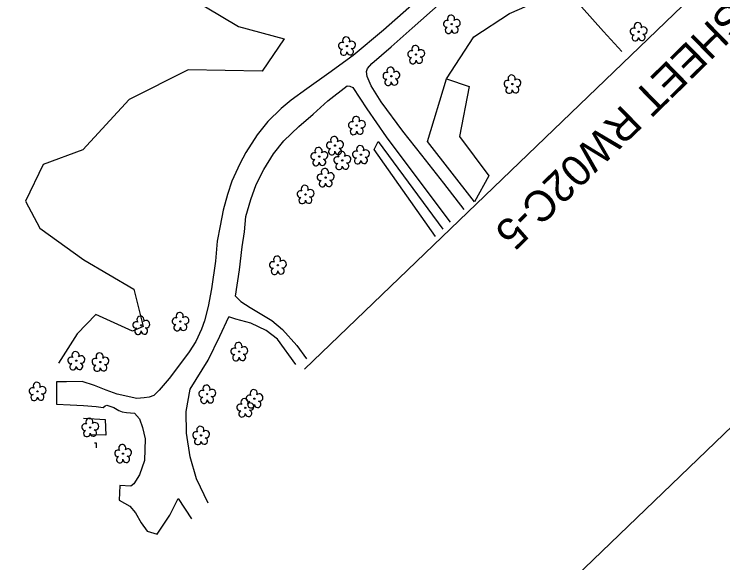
# Model space of a CAD drawing. Extents: x 473158 to 477500, y 500738 to 505114.
# Drawn here: x 475616.1 to 475983.4, y 501414.7 to 501699.2 of the extents above; entities that cross this region are included whole.
import ezdxf

# ---------------------------------------------------------------- set-up
doc = ezdxf.new("R2010")
doc.units = 0
for name, color, linetype in [('CTL Sheet Border CELL', 7, 'Continuous'), ('Exist Other Culture Area Outline', 7, 'Continuous'), ('Exist Roads Soil', 7, 'Continuous'), ('Exist Vegetation Hedge Row', 7, 'Continuous'), ('Exist Vegetation Tree CELL', 7, 'Continuous'), ('Exist Vegetation Woods Line', 7, 'Continuous'), ('Matchline', 7, 'Continuous'), ('Matchline Text', 7, 'Continuous')]:
    doc.layers.add(name, color=color, linetype=linetype)

msp = doc.modelspace()

# ---------------------------------------------------------------- linework, layer by layer
at = {"layer": 'CTL Sheet Border CELL'}
msp.add_lwpolyline([(473224.2, 503436.31), (475527.63, 501042.56), (477203.24, 502654.95), (474899.8, 505048.7)], close=True, dxfattribs=at)
at = {"layer": 'Exist Other Culture Area Outline'}
for points in [[(475651.96, 501489.64), (475663.24, 501489.08), (475663.53, 501480.96), (475655.8, 501481.12)], [(475658.85, 501474.35), (475658.86, 501476.71), (475657.76, 501476.76)]]:
    msp.add_lwpolyline(points, dxfattribs=at)
at = {"layer": 'Exist Roads Soil'}
for points in [[(475849.31, 501597.94), (475838.76, 501611.62), (475827.36, 501626.14), (475817.57, 501638.52), (475806.28, 501653.8), (475801.13, 501662.09), (475799.04, 501666.86), (475798.74, 501669.55), (475799.27, 501671.07), (475801.55, 501673.54), (475811.52, 501682.32), (475822.32, 501691.88), (475837.47, 501705.27), (475856.84, 501721.99), (475870.17, 501733), (475888.6, 501747.32), (475901.67, 501758.36), (475911.09, 501765.57), (475915.17, 501767.66), (475920.89, 501768.24), (475926.56, 501768.26)], [(475830.78, 501711.61), (475807.52, 501690.93), (475791.8, 501677.7), (475779.23, 501668.59), (475767.81, 501660.49), (475759.68, 501654.65), (475754.45, 501650.31), (475747.62, 501643.6), (475741.99, 501636.63)], [(475730.76, 501552.91), (475732.96, 501566.53), (475734.34, 501578.55), (475735.51, 501586.32), (475736.22, 501594.24), (475738.71, 501603.08), (475741.5, 501610.93), (475745.44, 501618.64), (475750.59, 501626.74), (475755.88, 501633.49), (475763.58, 501640.88), (475771.08, 501647.42), (475778.75, 501654.23), (475788.78, 501662.04), (475790.15, 501661.92), (475791.61, 501661.17), (475798.92, 501650.1), (475808.87, 501635.6), (475825.81, 501612.98), (475842.1, 501591.31)], [(475741.99, 501636.63), (475736.11, 501627.5), (475733.15, 501621.58), (475728.98, 501612.62), (475726.6, 501605.7), (475724.49, 501597.56), (475722.92, 501589.45), (475721.36, 501581.54), (475720.41, 501571.07), (475718.38, 501556.77), (475716.64, 501547.54), (475714.74, 501540.21), (475713.14, 501535.89), (475710.22, 501529.43), (475706.89, 501524.12), (475701.78, 501517.3), (475696.52, 501510.24), (475691.28, 501504.17), (475688.43, 501501.5), (475686.11, 501500.5), (475683.52, 501500.17), (475679.76, 501499.88), (475669.57, 501502.16), (475663.81, 501504.3), (475657.7, 501506.64), (475651.31, 501508.68), (475643.31, 501508.52), (475637.97, 501508.54), (475637.96, 501497.01), (475645.14, 501496.69), (475652.02, 501496.33), (475658.52, 501495.75), (475662.26, 501495.14), (475663.23, 501496.08), (475664.05, 501496.48), (475667.75, 501495.25), (475670.27, 501493.74), (475672, 501493), (475674.34, 501492.64), (475678.42, 501492.24), (475680.99, 501489.32), (475682.57, 501484.93), (475683.97, 501478.91), (475683.67, 501467.72), (475681.04, 501460.38), (475678.07, 501455.7), (475676.51, 501454.36), (475670.9, 501454.77), (475670.61, 501447.15), (475676.02, 501444.03), (475679, 501440.65), (475681.96, 501435.42), (475685.06, 501431.06), (475690.18, 501429.61), (475696.79, 501439.45), (475701.17, 501447.98), (475708.07, 501437.42)], [(475730.76, 501552.91), (475733.53, 501550.14), (475738.44, 501547.16), (475749.58, 501540.31), (475755.11, 501535.75), (475762.57, 501527.36), (475767.66, 501520.54)], [(475716.61, 501445.64), (475710.56, 501458.27), (475707.35, 501469.61), (475705.38, 501481.9), (475705.18, 501493.16), (475707.33, 501504.81), (475716.63, 501519.72), (475722.71, 501532.17), (475727.38, 501542.16)], [(475762.14, 501517.56), (475752.65, 501530.58), (475746.71, 501535.15), (475738.79, 501538.92), (475730.98, 501540.99), (475727.38, 501542.16)]]:
    msp.add_lwpolyline(points, dxfattribs=at)
at = {"layer": 'Exist Vegetation Hedge Row'}
msp.add_lwpolyline([(475840.13, 501665.63), (475854.3, 501687.47), (475872.85, 501699.59), (475897.94, 501710.57), (475904.37, 501709.63), (475921.52, 501690.15), (475931.11, 501679.81)], dxfattribs=at)
at = {"layer": 'Exist Vegetation Tree CELL'}
for p, q in [((475842.91, 501694.01), (475842.91, 501694.01)), ((475939.76, 501690.1), (475939.76, 501690.1)), ((475788.59, 501682.65), (475788.59, 501682.65)), ((475824.42, 501678.29), (475824.42, 501678.29)), ((475811.59, 501667.01), (475811.59, 501667.01)), ((475874.32, 501662.94), (475874.32, 501662.94)), ((475793.67, 501641.49), (475793.67, 501641.49)), ((475782.39, 501631.03), (475782.39, 501631.03)), ((475774.23, 501625.35), (475774.23, 501625.35)), ((475795.84, 501626.32), (475795.84, 501626.32)), ((475786.15, 501623.36), (475786.15, 501623.36)), ((475777.54, 501614.44), (475777.54, 501614.44)), ((475767.09, 501605.72), (475767.09, 501605.72)), ((475752.76, 501568.99), (475752.76, 501568.99)), ((475681.95, 501537.85), (475681.95, 501537.85)), ((475702.27, 501539.82), (475702.27, 501539.82)), ((475732.74, 501524.19), (475732.74, 501524.19)), ((475648.29, 501519.51), (475648.29, 501519.51)), ((475660.77, 501518.77), (475660.77, 501518.77)), ((475628.21, 501503.59), (475628.21, 501503.59)), ((475716.15, 501502.16), (475716.15, 501502.16)), ((475740.62, 501499.8), (475740.62, 501499.8)), ((475735.88, 501495.08), (475735.88, 501495.08)), ((475655.48, 501484.9), (475655.48, 501484.9)), ((475712.96, 501480.74), (475712.96, 501480.74)), ((475672.53, 501471.3), (475672.53, 501471.3))]:
    msp.add_line(p, q, dxfattribs=at)
for centre in [(475842.91, 501694.01), (475939.76, 501690.1), (475788.59, 501682.65), (475824.42, 501678.29), (475811.59, 501667.01), (475874.32, 501662.94), (475793.67, 501641.49), (475782.39, 501631.03), (475774.23, 501625.35), (475795.84, 501626.32), (475786.15, 501623.36), (475777.54, 501614.44), (475767.09, 501605.72), (475752.76, 501568.99), (475681.95, 501537.85), (475702.27, 501539.82), (475732.74, 501524.19), (475648.29, 501519.51), (475660.77, 501518.77), (475628.21, 501503.59), (475716.15, 501502.16), (475740.62, 501499.8), (475735.88, 501495.08), (475655.48, 501484.9), (475712.96, 501480.74), (475672.53, 501471.3)]:
    msp.add_circle(centre, 0.326, dxfattribs=at)
for centre, radius, start, end in [((475842.52, 501696.88), 1.86, 330.1651, 219.7134), ((475840.3, 501694.16), 1.73, 62.6636, 279.3457), ((475845.45, 501694.6), 1.9, 257.1011, 134.1999), ((475939.38, 501692.97), 1.86, 330.1651, 219.7134), ((475841.2, 501690.89), 1.69, 111.5671, 6.231), ((475844.58, 501691.11), 1.7, 181.2822, 74.56), ((475937.16, 501690.25), 1.73, 62.6636, 279.3457), ((475942.31, 501690.69), 1.9, 257.1011, 134.1999), ((475938.06, 501686.98), 1.69, 111.5671, 6.231), ((475941.43, 501687.2), 1.7, 181.2822, 74.56), ((475785.98, 501682.81), 1.73, 62.6636, 279.3457), ((475788.2, 501685.53), 1.86, 330.1651, 219.7134), ((475791.14, 501683.24), 1.9, 257.1011, 134.1999), ((475786.88, 501679.53), 1.69, 111.5671, 6.231), ((475790.26, 501679.75), 1.7, 181.2822, 74.56), ((475821.82, 501678.45), 1.73, 62.6636, 279.3457), ((475824.04, 501681.17), 1.86, 330.1651, 219.7134), ((475826.97, 501678.88), 1.9, 257.1011, 134.1999), ((475822.72, 501675.17), 1.69, 111.5671, 6.231), ((475826.09, 501675.4), 1.7, 181.2822, 74.56), ((475811.2, 501669.88), 1.86, 330.1651, 219.7134), ((475814.14, 501667.59), 1.9, 257.1011, 134.1999), ((475808.98, 501667.16), 1.73, 62.6636, 279.3457), ((475809.89, 501663.89), 1.69, 111.5671, 6.231), ((475813.26, 501664.11), 1.7, 181.2822, 74.56), ((475873.93, 501665.81), 1.86, 330.1651, 219.7134), ((475876.87, 501663.53), 1.9, 257.1011, 134.1999), ((475871.71, 501663.09), 1.73, 62.6636, 279.3457), ((475872.61, 501659.82), 1.69, 111.5671, 6.231), ((475875.99, 501660.04), 1.7, 181.2822, 74.56), ((475791.06, 501641.64), 1.73, 62.6636, 279.3457), ((475793.28, 501644.36), 1.86, 330.1651, 219.7134), ((475796.22, 501642.08), 1.9, 257.1011, 134.1999), ((475791.96, 501638.37), 1.69, 111.5671, 6.231), ((475795.34, 501638.59), 1.7, 181.2822, 74.56), ((475779.78, 501631.19), 1.73, 62.6636, 279.3457), ((475782, 501633.91), 1.86, 330.1651, 219.7134), ((475784.94, 501631.62), 1.9, 257.1011, 134.1999), ((475773.84, 501628.22), 1.86, 330.1651, 219.7134), ((475780.69, 501627.91), 1.69, 111.5671, 6.231), ((475784.06, 501628.13), 1.7, 181.2822, 74.56), ((475795.45, 501629.19), 1.86, 330.1651, 219.7134), ((475798.39, 501626.91), 1.9, 257.1011, 134.1999), ((475771.62, 501625.51), 1.73, 62.6636, 279.3457), ((475776.78, 501625.94), 1.9, 257.1011, 134.1999), ((475783.55, 501623.51), 1.73, 62.6636, 279.3457), ((475785.77, 501626.23), 1.86, 330.1651, 219.7134), ((475788.7, 501623.95), 1.9, 257.1011, 134.1999), ((475793.23, 501626.47), 1.73, 62.6636, 279.3457), ((475797.51, 501623.42), 1.7, 181.2822, 74.56), ((475772.52, 501622.23), 1.69, 111.5671, 6.231), ((475775.9, 501622.45), 1.7, 181.2822, 74.56), ((475784.45, 501620.24), 1.69, 111.5671, 6.231), ((475787.83, 501620.46), 1.7, 181.2822, 74.56), ((475794.13, 501623.2), 1.69, 111.5671, 6.231), ((475777.16, 501617.31), 1.86, 330.1651, 219.7134), ((475774.94, 501614.59), 1.73, 62.6636, 279.3457), ((475780.09, 501615.03), 1.9, 257.1011, 134.1999), ((475766.7, 501608.6), 1.86, 330.1651, 219.7134), ((475775.84, 501611.32), 1.69, 111.5671, 6.231), ((475779.22, 501611.54), 1.7, 181.2822, 74.56), ((475764.48, 501605.88), 1.73, 62.6636, 279.3457), ((475769.64, 501606.31), 1.9, 257.1011, 134.1999), ((475765.39, 501602.6), 1.69, 111.5671, 6.231), ((475768.76, 501602.82), 1.7, 181.2822, 74.56), ((475752.37, 501571.86), 1.86, 330.1651, 219.7134), ((475750.15, 501569.14), 1.73, 62.6636, 279.3457), ((475755.3, 501569.58), 1.9, 257.1011, 134.1999), ((475751.05, 501565.87), 1.69, 111.5671, 6.231), ((475754.43, 501566.09), 1.7, 181.2822, 74.56), ((475701.88, 501542.69), 1.86, 330.1651, 219.7134), ((475681.56, 501540.73), 1.86, 330.1651, 219.7134), ((475699.66, 501539.97), 1.73, 62.6636, 279.3457), ((475704.82, 501540.41), 1.9, 257.1011, 134.1999), ((475679.34, 501538.01), 1.73, 62.6636, 279.3457), ((475684.5, 501538.44), 1.9, 257.1011, 134.1999), ((475700.56, 501536.7), 1.69, 111.5671, 6.231), ((475703.94, 501536.92), 1.7, 181.2822, 74.56), ((475680.25, 501534.73), 1.69, 111.5671, 6.231), ((475683.62, 501534.95), 1.7, 181.2822, 74.56), ((475730.14, 501524.35), 1.73, 62.6636, 279.3457), ((475732.36, 501527.07), 1.86, 330.1651, 219.7134), ((475735.29, 501524.78), 1.9, 257.1011, 134.1999), ((475647.9, 501522.38), 1.86, 330.1651, 219.7134), ((475660.38, 501521.65), 1.86, 330.1651, 219.7134), ((475731.04, 501521.07), 1.69, 111.5671, 6.231), ((475734.42, 501521.29), 1.7, 181.2822, 74.56), ((475645.68, 501519.66), 1.73, 62.6636, 279.3457), ((475650.84, 501520.1), 1.9, 257.1011, 134.1999), ((475658.16, 501518.93), 1.73, 62.6636, 279.3457), ((475663.32, 501519.36), 1.9, 257.1011, 134.1999), ((475646.58, 501516.39), 1.69, 111.5671, 6.231), ((475649.96, 501516.61), 1.7, 181.2822, 74.56), ((475659.06, 501515.65), 1.69, 111.5671, 6.231), ((475662.44, 501515.87), 1.7, 181.2822, 74.56), ((475627.82, 501506.46), 1.86, 330.1651, 219.7134), ((475625.6, 501503.74), 1.73, 62.6636, 279.3457), ((475630.75, 501504.18), 1.9, 257.1011, 134.1999), ((475713.54, 501502.32), 1.73, 62.6636, 279.3457), ((475715.77, 501505.03), 1.86, 330.1651, 219.7134), ((475718.7, 501502.75), 1.9, 257.1011, 134.1999), ((475740.23, 501502.67), 1.86, 330.1651, 219.7134), ((475626.5, 501500.47), 1.69, 111.5671, 6.231), ((475629.88, 501500.69), 1.7, 181.2822, 74.56), ((475714.45, 501499.04), 1.69, 111.5671, 6.231), ((475717.82, 501499.26), 1.7, 181.2822, 74.56), ((475738.01, 501499.95), 1.73, 62.6636, 279.3457), ((475743.17, 501500.39), 1.9, 257.1011, 134.1999), ((475733.28, 501495.24), 1.73, 62.6636, 279.3457), ((475735.5, 501497.96), 1.86, 330.1651, 219.7134), ((475738.43, 501495.67), 1.9, 257.1011, 134.1999), ((475738.91, 501496.68), 1.69, 111.5671, 6.231), ((475742.29, 501496.9), 1.7, 181.2822, 74.56), ((475734.18, 501491.96), 1.69, 111.5671, 6.231), ((475737.55, 501492.18), 1.7, 181.2822, 74.56), ((475655.09, 501487.77), 1.86, 330.1651, 219.7134), ((475652.87, 501485.05), 1.73, 62.6636, 279.3457), ((475658.03, 501485.49), 1.9, 257.1011, 134.1999), ((475712.58, 501483.61), 1.86, 330.1651, 219.7134), ((475653.78, 501481.78), 1.69, 111.5671, 6.231), ((475657.15, 501482), 1.7, 181.2822, 74.56), ((475710.35, 501480.89), 1.73, 62.6636, 279.3457), ((475715.51, 501481.33), 1.9, 257.1011, 134.1999), ((475711.26, 501477.62), 1.69, 111.5671, 6.231), ((475714.63, 501477.84), 1.7, 181.2822, 74.56), ((475672.14, 501474.17), 1.86, 330.1651, 219.7134), ((475669.92, 501471.45), 1.73, 62.6636, 279.3457), ((475675.07, 501471.89), 1.9, 257.1011, 134.1999), ((475670.82, 501468.18), 1.69, 111.5671, 6.231), ((475674.2, 501468.4), 1.7, 181.2822, 74.56)]:
    msp.add_arc(centre, radius, start, end, dxfattribs=at)
at = {"layer": 'Exist Vegetation Woods Line'}
for p, q in [((475802.63, 501629.02), (475804.73, 501633.22)), ((475804.73, 501633.22), (475838.31, 501587.65)), ((475834.49, 501583.91), (475802.63, 501629.02))]:
    msp.add_line(p, q, dxfattribs=at)
for points in [[(475699.09, 501712.78), (475732.29, 501692.73), (475756.01, 501686.38), (475744.7, 501669.63), (475706.33, 501670.34), (475675.71, 501655.01), (475651.73, 501628.83), (475631.16, 501621.18), (475621.91, 501602.2), (475629.48, 501588.19), (475652.23, 501571.79), (475678.14, 501556.57), (475682.89, 501537.29), (475677.52, 501534.81), (475658.45, 501543.53), (475648.82, 501533.5), (475639.08, 501518.21)], [(475854.76, 501601.86), (475830.28, 501633.21), (475840.13, 501665.63)], [(475840.13, 501665.63), (475851.95, 501661.74), (475846.92, 501635.81), (475862.08, 501615.44), (475854.76, 501601.86)]]:
    msp.add_lwpolyline(points, dxfattribs=at)
at = {"layer": 'Matchline'}
msp.add_line((475766.52, 501515.03), (476126.81, 501861.72), dxfattribs=at)

# ---------------------------------------------------------------- texts
at = {"layer": 'Matchline Text'}
msp.add_text('MATCHLINE SHEET RW02C-5', height=16, rotation=224.2987, dxfattribs=at).set_placement((476079.51, 501797.32))

doc.saveas('drawing.dxf')
